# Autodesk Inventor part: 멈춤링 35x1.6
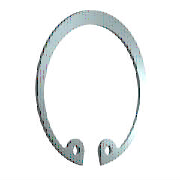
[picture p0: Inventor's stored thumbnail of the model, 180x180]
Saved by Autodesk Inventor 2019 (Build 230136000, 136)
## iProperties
IsCustomPart: 1
Created: 2012-02
Part Number: 멈춤링 35x1.6
Material: 강철, 연강
Description: 리테이닝 링(C형)
Document SubType Name: Modeling
Standard: KS B 1336
Designer: mduedu
Standards Organization: KS
Language: ko-KR
Size Designation: 35x1.6
Categories: <MemberInstance><Categories><Category DisplayName="샤프트 부품" InternalName="7f7aeb1f-a693-4053-b835-cee3144e0d98" Mnemonic="SHFT"><Category DisplayName="써클립" Inter
Density: 1 g/cm^3
Appearance: 파란색 - 벽 페인트 - 광택
Author: mduedu
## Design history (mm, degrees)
sketch "스케치1"
  geometry: L1 (0, 15.113)-(0, -73.177) reference; L2 (-45.5, 0)-(45.5, 0) reference; L3 (-4.964, 1)-(1.502, 1); L4 (0, -2.5)-(-5.307, -2.5); L5 (0, -17.5)-(-8.583, -33.888); L6 (-8.583, -33.888)-(-21.772, -26.981); L7 (-7.377, -31.585)-(-17.631, -26.214); L8 (-5.162, -32.745)-(-6.29, -34.898); L9 (5.162, -32.745)-(6.29, -34.898); C1 r 1.25 at (-7.377, -31.585); C2 r 1.25 at (7.377, -31.585); A1 r 15.875 centre (0, -18.375) between (11.82, -28.972) and (-11.82, -28.972); A2 r 18.5 centre (0, -17.5) between (6.29, -34.898) and (-6.29, -34.898); A3 r 2.5 centre (-7.377, -31.585) between (-5.162, -32.745) and (-8.668, -29.444); A4 r 2.5 centre (-9.959, -27.303) between (-11.82, -28.972) and (-8.668, -29.444); A5 r 2.5 centre (9.959, -27.303) between (8.668, -29.444) and (11.82, -28.972); A6 r 2.5 centre (7.377, -31.585) between (8.668, -29.444) and (5.162, -32.745); 3 further points
  constraints: 15 point on circle, 14 end point, 9 symmetric about line, 8 centre point, 6 tangent, 4 coincident, 4 point on line, 3 perpendicular, 1 parallel, 4 other
  dimensions: "d8" = 0.875 distance of A1.centre L5.start (= 0.25 x SRB1); "d38" = 3.5 distance between parallel lines of L4 L3 (= SRB1); "d39" = 17.5 distance from line of L5.start L2 (= 0.5 x WD); "d43" = 18.5 radius of A2 (= 0.5 x ND); "d45" = 2.6 distance between parallel lines of L7 L6 (= 0.5 x SRB2); "d46" = 2.5 radius of A4 (= SD5); "d47" = 6.29 distance from line of L1 L8.end (= 0.17 x ND); "d48" = 2.5 diameter of C1 (= SD5); "d49" = 2.5 radius of A3 (= SD5)
extrude "본체" new body sketch "스케치1" distance "d2" = 1.6 (= SD); taper "d3" = 0 deg
workaxis "Work Axis1"
workaxis "Work Axis2"
workplane "Work Plane1"
body "Solid1"
other parameters: "WD" = 35 [user parameter; used in 3 equation terms], "SD" = 1.6 [user parameter; used in 1 equation term], "SRB1" = 3.5 [user parameter; used in 2 equation terms], "ND" = 37 [user parameter; used in 2 equation terms], "SRB2" = 5.2 [user parameter; used in 1 equation term], "SD5" = 2.5 [user parameter; used in 3 equation terms], "d50" = 0, "d51" = 0, "d52" = 0, "d53" = 0, "WDMIN" = 34 [user parameter], "SD6" = 37.8 [user parameter], "WDMAX" = 35 (= WD) [user parameter], "NND" = 35 (= WD) [user parameter]
